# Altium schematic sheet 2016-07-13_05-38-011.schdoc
size 313 x 134 mm; SheetNumber: 1; SheetTotal: 1
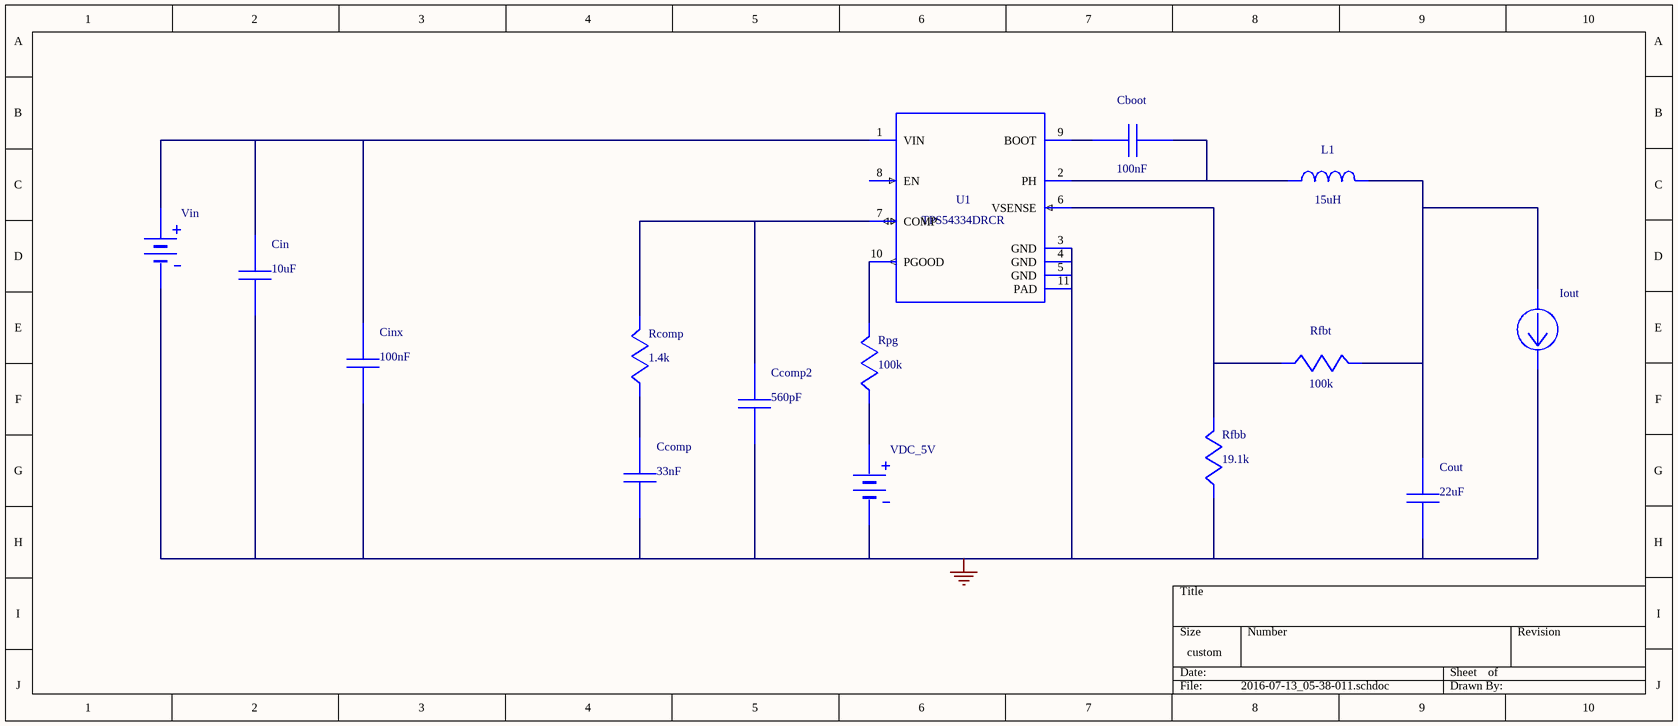
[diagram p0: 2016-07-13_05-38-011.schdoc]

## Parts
Cboot  value 100nF  (hidden comment: C0805C104K5RACTU)
Ccomp  value 33nF  (hidden comment: GRM033R60J333KE01D)
Ccomp2  value 560pF  (hidden comment: CC0805KRX7R9BB561)
Cin  value 10uF  (hidden comment: GRM21BR61C106KE15L)
Cinx  value 100nF  (hidden comment: C0805C104K5RACTU)
Cout  value 22uF  (hidden comment: GRM31CR61A226KE19L)
Iout  WB_CURRENT_LOAD  (value not drawn)
L1  value 15uH  (hidden comment: VLP8040T-150M)
Rcomp  value 1.4k  (hidden comment: CRCW04021K40FKED)
Rfbb  value 19.1k  (hidden comment: CRCW040219K1FKED)
Rfbt  value 100k  (hidden comment: CRCW0402100KFKED)
Rpg  value 100k  (hidden comment: CRCW0402100KFKED)
U1  TPS54334DRCR
VDC_5V  WB_PRIM_DC_VOLTAGE_SOURCE  (value not drawn)
Vin  WB_BATTERY  (value not drawn)

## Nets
0: Ccomp.2 Ccomp2.2 Cin.2 Cinx.2 Cout.2 Iout.2(-) Rfbb.2 U1.3(GND) U1.4(GND) U1.5(GND) U1.11(PAD) VDC_5V.2(-) Vin.2(-)
NetCboot_1: Cboot.1 U1.9(BOOT)
NetCboot_2: Cboot.2 L1.1 U1.2(PH)
NetCcomp2_1: Ccomp2.1 Rcomp.1 U1.7(COMP)
NetCcomp_1: Ccomp.1 Rcomp.2
NetCin_1: Cin.1 Cinx.1 U1.1(VIN) Vin.1(+)
NetCout_1: Cout.1 Iout.1(+) L1.2 Rfbt.1
NetRfbb_1: Rfbb.1 Rfbt.2 U1.6(VSENSE)
NetRpg_1: Rpg.1 U1.10(PGOOD)
NetRpg_2: Rpg.2 VDC_5V.1(+)

Not connected (* = marked no-connect by the designer): U1 8(EN)

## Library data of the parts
Cboot Cinx = C0805C104K5RACTU: Manufacturer Name: Kemet
Ccomp = GRM033R60J333KE01D: GRM033R60J333KE0; Manufacturer Name: MuRata
Ccomp2 = CC0805KRX7R9BB561: CC0805KRX7R9BB56; Manufacturer Name: Yageo America
Cin = GRM21BR61C106KE15L: GRM21BR61C106KE1; Manufacturer Name: MuRata
Cout = GRM31CR61A226KE19L: GRM31CR61A226KE1; Manufacturer Name: MuRata
L1 = VLP8040T-150M: Unknown; Manufacturer Name: TDK
Rcomp = CRCW04021K40FKED: Manufacturer Name: Vishay-Dale
Rfbb = CRCW040219K1FKED: Manufacturer Name: Vishay-Dale
Rfbt Rpg = CRCW0402100KFKED: Manufacturer Name: Vishay-Dale
U1 = TPS54334DRCR: Manufacturer Name: Texas Instruments
VDC_5V = WB_PRIM_DC_VOLTAGE_SOURCE: WB_PRIM_DC_VOLTA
